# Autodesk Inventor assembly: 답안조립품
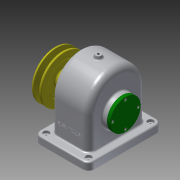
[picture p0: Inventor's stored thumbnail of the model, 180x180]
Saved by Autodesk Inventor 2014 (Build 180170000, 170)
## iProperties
Created: 2016-10
Part Number: 답안조립품
Document SubType Name: Assembly
Designer: USER
Author: USER
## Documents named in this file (15)
- C:\Users\USER\Desktop\461008V1018\답안조립품.iam
- C:\Users\USER\Desktop\461008V1018\V-벨트풀리.ipt
- C:\Users\USER\Desktop\461008V1018\뒤커버.ipt
- C:\Users\USER\Desktop\461008V1018\멈춤나사 - M4x10.ipt
- C:\Users\USER\Desktop\461008V1018\본체.ipt
- C:\Users\USER\Desktop\461008V1018\부시.ipt
- C:\Users\USER\Desktop\461008V1018\스퍼기어.ipt
- C:\Users\USER\Desktop\461008V1018\앞커버.ipt
- C:\Users\USER\Desktop\461008V1018\오일씰 28 40 8.ipt
- C:\Users\USER\Desktop\461008V1018\축.ipt
- C:\Users\USER\Desktop\461008V1018\키 - 5 x 5 x 18.ipt
- C:\Users\USER\Desktop\461008V1018\키 - 6 x 6 x 22.ipt
- C:\Users\USER\Desktop\461008V1018\베어링 6203.ipt
- C:\Users\USER\Desktop\461008V1018\볼트 M3 x 8.ipt
- C:\Users\USER\Desktop\461008V1018\볼트 M3 x 10.ipt
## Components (9 placed, 3 different names)
1. V-벨트풀리:1 — 각도:1
2. ISO 4762 M3 x 10:1
3. ISO 4762 M3 x 10:2
4. ISO 4762 M3 x 10:3
5. ISO 4762 M3 x 10:4
6. ISO 4762 M3 x 8:1
7. ISO 4762 M3 x 8:2
8. ISO 4762 M3 x 8:3
9. ISO 4762 M3 x 8:4
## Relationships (1: Angle 1)
- 각도:1 [Angle]: V-벨트풀리:1
